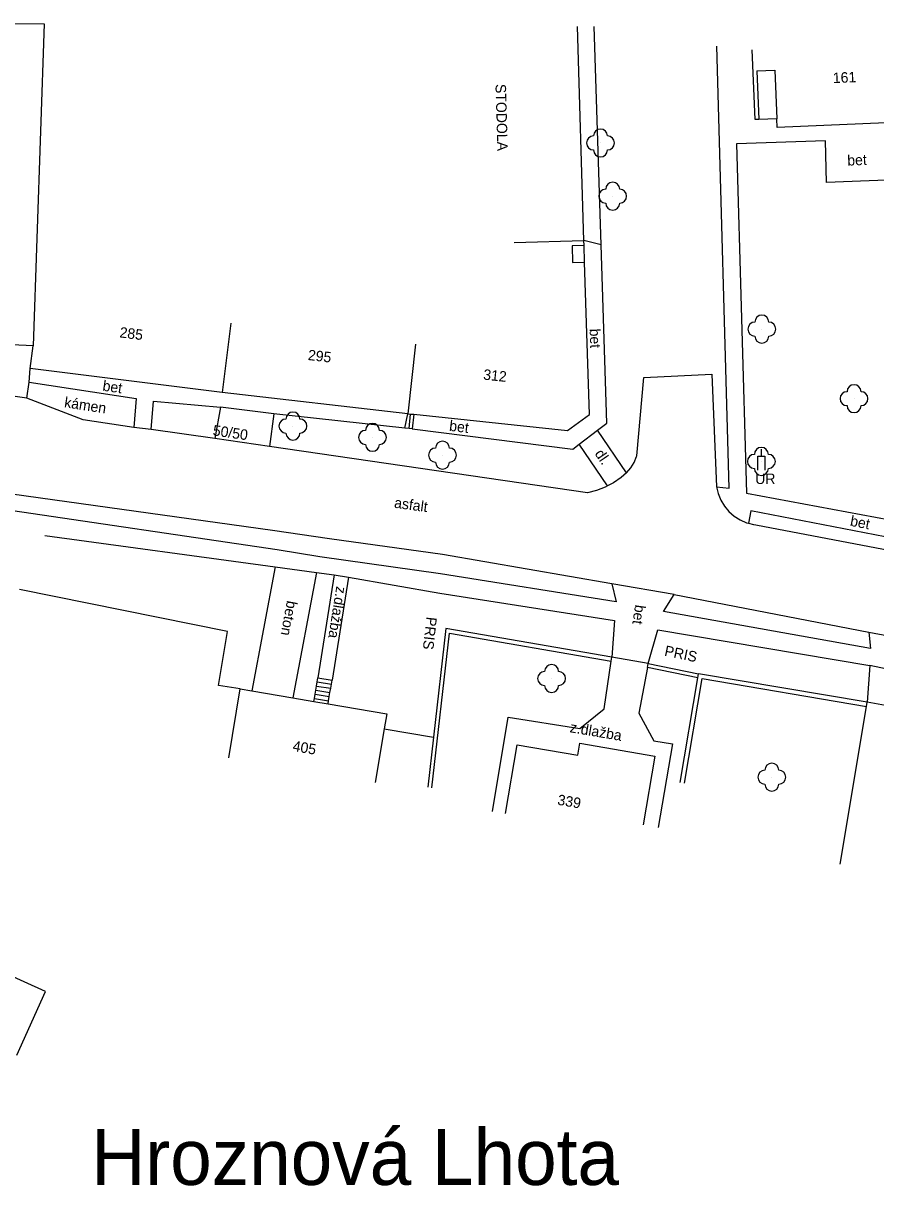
# Model space of a CAD drawing. Extents: x -544674 to -541478, y -1199076 to -1195527.
# Drawn here: x -542446 to -542385, y -1198636.5 to -1198553.3 of the extents above; entities that cross this region are included whole.
import ezdxf

# ---------------------------------------------------------------- set-up
doc = ezdxf.new("R2010")
doc.units = 0
for name, color, linetype in [('BUDOVY_MĚŘ', 7, 'Continuous'), ('BUDOVY_NEMĚŘ', 7, 'Continuous'), ('NÁZVY_SÍDEL_JEDNOTKY', 7, 'Continuous'), ('POMOC_POPIS', 7, 'Continuous'), ('ROZHRANÍ_PLOCH', 7, 'Continuous'), ('ZELEŇ', 7, 'Continuous'), ('ZN_DOPLŇKOVÉ', 7, 'Continuous'), ('Č_POPIS_ORIENT', 7, 'Continuous')]:
    doc.layers.add(name, color=color, linetype=linetype)

msp = doc.modelspace()

# ---------------------------------------------------------------- linework, layer by layer
at = {"layer": 'BUDOVY_MĚŘ'}
for points in [[(-542405.91, -1198568.84), (-542406.36, -1198553.52)], [(-542393.39, -1198560.18), (-542393.65, -1198560.19), (-542393.86, -1198555.2)], [(-542392.1, -1198560.12), (-542393.39, -1198560.18)], [(-542382.62, -1198560.35), (-542392.07, -1198560.75), (-542392.1, -1198560.12)], [(-542410.91, -1198568.99), (-542405.91, -1198568.84)], [(-542405.9, -1198569.2), (-542406.76, -1198569.23), (-542406.72, -1198570.42), (-542405.86, -1198570.39)], [(-542405.9, -1198569.2), (-542405.91, -1198568.84)], [(-542405.86, -1198570.39), (-542405.9, -1198569.2)], [(-542418.09, -1198581.28), (-542407.08, -1198582.45), (-542405.5, -1198581.29), (-542405.86, -1198570.39)], [(-542431.17, -1198574.75), (-542431.79, -1198579.71)], [(-542445.33, -1198576.39), (-542457.12, -1198575.82)], [(-542445.53, -1198578), (-542445.33, -1198576.39)], [(-542417.97, -1198576.27), (-542418.5, -1198581.24)], [(-542431.79, -1198579.71), (-542445.53, -1198578)], [(-542418.5, -1198581.24), (-542431.79, -1198579.71)], [(-542418.5, -1198581.24), (-542418.31, -1198581.26)], [(-542418.31, -1198581.26), (-542418.09, -1198581.28)], [(-542431.33, -1198605.87), (-542430.5, -1198600.94)], [(-542430.5, -1198600.94), (-542429.68, -1198601.08)], [(-542429.68, -1198601.08), (-542426.74, -1198601.58)], [(-542426.74, -1198601.58), (-542425.23, -1198601.83)], [(-542425.23, -1198601.83), (-542424.22, -1198602)], [(-542424.22, -1198602), (-542420.02, -1198602.71), (-542420.2, -1198603.79)], [(-542420.2, -1198603.79), (-542420.85, -1198607.64)], [(-542411.53, -1198609.86), (-542410.69, -1198604.93), (-542406.34, -1198605.67), (-542406.2, -1198604.83), (-542400.84, -1198605.74), (-542401.68, -1198610.67)], [(-542446.48, -1198627.16), (-542444.43, -1198622.6), (-542457.73, -1198616.59), (-542462.9, -1198628.04), (-542468.83, -1198625.36), (-542470.08, -1198628.13), (-542475.77, -1198625.55), (-542478.86, -1198632.49)]]:
    msp.add_lwpolyline(points, dxfattribs=at)
at = {"layer": 'BUDOVY_NEMĚŘ'}
msp.add_lwpolyline([(-542463.23, -1198565.44), (-542463.38, -1198567.01), (-542456.99, -1198567.62), (-542456.68, -1198564.4), (-542454.54, -1198564.6), (-542453.46, -1198553.29), (-542444.54, -1198553.32), (-542445.33, -1198576.39)], dxfattribs=at)
at = {"layer": 'ROZHRANÍ_PLOCH'}
for points in [[(-542404.67, -1198569.15), (-542405.17, -1198553.52)], [(-542396.41, -1198586.46), (-542395.51, -1198586.57), (-542396.39, -1198554.92)], [(-542393.54, -1198556.69), (-542392.24, -1198556.64)], [(-542393.54, -1198556.69), (-542393.39, -1198560.18)], [(-542392.24, -1198556.64), (-542392.1, -1198560.12)], [(-542382.62, -1198560.35), (-542382.44, -1198564.45), (-542388.56, -1198564.68), (-542388.63, -1198561.71), (-542394.99, -1198561.92), (-542394.27, -1198586.92), (-542371.71, -1198591.13), (-542371.39, -1198572.75), (-542373.05, -1198561.12), (-542375.01, -1198561.22), (-542375.06, -1198560.04)], [(-542404.67, -1198569.15), (-542405.91, -1198568.84)], [(-542404.93, -1198582.42), (-542404.27, -1198581.92), (-542404.67, -1198569.15)], [(-542445.77, -1198580.13), (-542468.76, -1198576.82)], [(-542445.6, -1198578.99), (-542445.53, -1198578)], [(-542402.85, -1198585.46), (-542402.55, -1198585.12), (-542402.31, -1198584.73), (-542402.14, -1198584.3), (-542402.13, -1198584.25), (-542401.61, -1198578.64), (-542396.75, -1198578.4), (-542396.41, -1198586.46)], [(-542445.77, -1198580.13), (-542445.6, -1198578.99)], [(-542445.6, -1198578.99), (-542437.95, -1198580.15), (-542438.11, -1198582.22)], [(-542438.11, -1198582.22), (-542441.74, -1198581.67), (-542445.77, -1198580.13)], [(-542436.87, -1198582.37), (-542436.71, -1198580.34), (-542431.92, -1198580.77)], [(-542431.92, -1198580.77), (-542432.31, -1198583.01)], [(-542428.11, -1198581.25), (-542431.92, -1198580.77)], [(-542428.11, -1198581.25), (-542428.42, -1198583.58)], [(-542418.72, -1198582.27), (-542428.11, -1198581.25)], [(-542418.72, -1198582.27), (-542418.5, -1198581.24)], [(-542436.87, -1198582.37), (-542438.11, -1198582.22)], [(-542432.31, -1198583.01), (-542436.87, -1198582.37)], [(-542418.42, -1198582.3), (-542418.72, -1198582.27)], [(-542418.2, -1198582.32), (-542406.71, -1198583.77), (-542406.25, -1198583.42)], [(-542406.25, -1198583.42), (-542404.93, -1198582.42)], [(-542402.85, -1198585.46), (-542404.93, -1198582.42)], [(-542428.42, -1198583.58), (-542432.31, -1198583.01)], [(-542404.21, -1198586.4), (-542404.38, -1198586.49), (-542405.01, -1198586.73), (-542405.66, -1198586.9), (-542428.42, -1198583.58)], [(-542404.21, -1198586.4), (-542406.25, -1198583.42)], [(-542402.85, -1198585.46), (-542403.24, -1198585.8), (-542403.79, -1198586.18), (-542404.21, -1198586.4)], [(-542396.41, -1198586.46), (-542396.3, -1198586.95), (-542396.12, -1198587.42), (-542395.86, -1198587.85), (-542395.54, -1198588.24), (-542395.16, -1198588.57), (-542394.73, -1198588.84), (-542394.27, -1198589.04), (-542394.12, -1198589.07)], [(-542403.91, -1198593.41), (-542416.02, -1198591.31), (-542424.11, -1198590.2), (-542428.2, -1198589.59), (-542446.85, -1198587), (-542447.58, -1198588.07)], [(-542403.91, -1198593.41), (-542403.6, -1198594.71), (-542416.17, -1198592.7), (-542424.81, -1198591.48), (-542427.85, -1198590.99), (-542447.58, -1198588.07)], [(-542372.45, -1198593.23), (-542371.79, -1198592.49), (-542393.96, -1198588.19), (-542394.12, -1198589.07)], [(-542394.12, -1198589.07), (-542393.78, -1198589.16), (-542393.61, -1198589.18), (-542372.45, -1198593.23)], [(-542444.48, -1198589.95), (-542428.01, -1198592.19)], [(-542428.01, -1198592.19), (-542429.68, -1198601.08)], [(-542428.01, -1198592.19), (-542425.05, -1198592.6)], [(-542425.05, -1198592.6), (-542426.74, -1198601.58)], [(-542425.05, -1198592.6), (-542423.77, -1198592.77)], [(-542423.77, -1198592.77), (-542424.94, -1198600.14)], [(-542423.77, -1198592.77), (-542422.76, -1198592.93)], [(-542422.76, -1198592.93), (-542423.93, -1198600.3)], [(-542422.76, -1198592.93), (-542416.21, -1198594.09), (-542403.72, -1198596.03), (-542403.92, -1198598.66)], [(-542399.44, -1198594.18), (-542403.91, -1198593.41)], [(-542385.53, -1198596.88), (-542385.41, -1198598.05), (-542400.22, -1198595.39), (-542399.44, -1198594.18)], [(-542399.44, -1198594.18), (-542385.53, -1198596.88)], [(-542401.3, -1198599.12), (-542400.63, -1198596.71), (-542385.44, -1198599.27)], [(-542385.53, -1198596.88), (-542381.04, -1198597.7)], [(-542412.46, -1198609.7), (-542411.32, -1198602.96), (-542406.2, -1198603.78), (-542404.47, -1198602.35), (-542403.97, -1198598.96)], [(-542401.36, -1198599.41), (-542401.97, -1198602.68), (-542400.9, -1198604.66), (-542399.58, -1198604.86), (-542400.6, -1198610.85)], [(-542385.44, -1198599.27), (-542385.63, -1198601.89)], [(-542381.97, -1198599.99), (-542385.44, -1198599.27)], [(-542424.99, -1198600.44), (-542424.94, -1198600.14)], [(-542424.94, -1198600.14), (-542423.93, -1198600.3)], [(-542425.14, -1198601.32), (-542425.09, -1198601.03)], [(-542425.09, -1198601.03), (-542425.04, -1198600.73)], [(-542425.09, -1198601.03), (-542424.08, -1198601.19)], [(-542425.04, -1198600.73), (-542424.99, -1198600.44)], [(-542425.04, -1198600.73), (-542424.03, -1198600.89)], [(-542424.99, -1198600.44), (-542423.98, -1198600.6)], [(-542424.08, -1198601.19), (-542424.03, -1198600.89)], [(-542424.03, -1198600.89), (-542423.98, -1198600.6)], [(-542423.98, -1198600.6), (-542423.93, -1198600.3)], [(-542425.23, -1198601.83), (-542425.19, -1198601.62)], [(-542425.19, -1198601.62), (-542425.14, -1198601.32)], [(-542425.19, -1198601.62), (-542424.18, -1198601.78)], [(-542425.14, -1198601.32), (-542424.13, -1198601.48)], [(-542424.22, -1198602), (-542424.18, -1198601.78)], [(-542424.18, -1198601.78), (-542424.13, -1198601.48)], [(-542424.13, -1198601.48), (-542424.08, -1198601.19)], [(-542387.57, -1198613.49), (-542385.68, -1198602.19)], [(-542420.2, -1198603.79), (-542416.67, -1198604.38)]]:
    msp.add_lwpolyline(points, dxfattribs=at)
at = {"layer": 'ZELEŇ'}
for centre in [(-542404.72, -1198561.86), (-542403.85, -1198565.67), (-542393.18, -1198575.18), (-542386.58, -1198580.16), (-542426.73, -1198582.12), (-542421.04, -1198582.93), (-542416.03, -1198584.2), (-542393.21, -1198584.65), (-542408.22, -1198600.19), (-542392.46, -1198607.25)]:
    msp.add_circle(centre, 0.0005, dxfattribs=at)
for centre, start, end in [((-542404.72, -1198561.36), 0, 179.99999), ((-542405.22, -1198561.86), 89.99999, 269.99999), ((-542404.22, -1198561.86), 270, 89.99999), ((-542404.72, -1198562.36), 179.99999, 359.99999), ((-542404.35, -1198565.67), 89.99999, 269.99999), ((-542403.85, -1198565.17), 0, 179.99999), ((-542403.35, -1198565.67), 270, 89.99999), ((-542403.85, -1198566.17), 179.99999, 359.99999), ((-542393.18, -1198574.68), 0, 179.99999), ((-542393.68, -1198575.18), 89.99999, 269.99999), ((-542392.68, -1198575.18), 270, 89.99999), ((-542393.18, -1198575.68), 179.99999, 359.99999), ((-542386.58, -1198579.66), 0, 179.99999), ((-542387.08, -1198580.16), 89.99999, 269.99999), ((-542386.08, -1198580.16), 270, 89.99999), ((-542426.73, -1198581.62), 0, 179.99999), ((-542386.58, -1198580.66), 179.99999, 359.99999), ((-542427.23, -1198582.12), 89.99999, 269.99999), ((-542426.23, -1198582.12), 270, 89.99999), ((-542421.04, -1198582.43), 0, 179.99999), ((-542426.73, -1198582.62), 179.99999, 359.99999), ((-542421.54, -1198582.93), 89.99999, 269.99999), ((-542420.54, -1198582.93), 270, 89.99999), ((-542421.04, -1198583.43), 179.99999, 359.99999), ((-542416.03, -1198583.7), 0, 179.99999), ((-542393.21, -1198584.15), 0, 179.99999), ((-542416.53, -1198584.2), 89.99999, 269.99999), ((-542415.53, -1198584.2), 270, 89.99999), ((-542393.71, -1198584.65), 89.99999, 269.99999), ((-542392.71, -1198584.65), 270, 89.99999), ((-542416.03, -1198584.7), 179.99999, 359.99999), ((-542393.21, -1198585.15), 179.99999, 359.99999), ((-542408.22, -1198599.69), 0, 179.99999), ((-542408.72, -1198600.19), 89.99999, 269.99999), ((-542407.72, -1198600.19), 270, 89.99999), ((-542408.22, -1198600.69), 179.99999, 359.99999), ((-542392.96, -1198607.25), 89.99999, 269.99999), ((-542392.46, -1198606.75), 0, 179.99999), ((-542391.96, -1198607.25), 270, 89.99999), ((-542392.46, -1198607.75), 179.99999, 359.99999)]:
    msp.add_arc(centre, 0.5, start, end, dxfattribs=at)
at = {"layer": 'ZN_DOPLŇKOVÉ'}
msp.add_line((-542393.21, -1198584.27), (-542393.21, -1198583.77), dxfattribs=at)
for points in [[(-542418.42, -1198582.3), (-542418.31, -1198581.26)], [(-542418.09, -1198581.28), (-542418.2, -1198582.32)], [(-542418.2, -1198582.32), (-542418.42, -1198582.3)], [(-542393.46, -1198585.27), (-542393.46, -1198584.27), (-542392.96, -1198584.27), (-542392.96, -1198585.27)], [(-542430.5, -1198600.94), (-542432.07, -1198600.69), (-542431.41, -1198596.82), (-542446.29, -1198593.81)], [(-542416.78, -1198608.01), (-542415.52, -1198596.95), (-542403.97, -1198598.96)], [(-542403.92, -1198598.66), (-542415.78, -1198596.6), (-542416.67, -1198604.38)], [(-542403.97, -1198598.96), (-542403.92, -1198598.66)], [(-542401.3, -1198599.12), (-542403.92, -1198598.66)], [(-542401.36, -1198599.41), (-542401.3, -1198599.12)], [(-542397.75, -1198600.15), (-542401.36, -1198599.41)], [(-542401.3, -1198599.12), (-542397.7, -1198599.85)], [(-542399.02, -1198607.63), (-542397.75, -1198600.15)], [(-542398.72, -1198607.68), (-542397.45, -1198600.2), (-542385.68, -1198602.19)], [(-542397.75, -1198600.15), (-542397.7, -1198599.85)], [(-542385.63, -1198601.89), (-542397.7, -1198599.85)], [(-542385.68, -1198602.19), (-542385.63, -1198601.89)], [(-542382.75, -1198602.4), (-542385.63, -1198601.89)], [(-542416.67, -1198604.38), (-542417.08, -1198607.97)]]:
    msp.add_lwpolyline(points, dxfattribs=at)

# ---------------------------------------------------------------- texts
at = {"layer": 'NÁZVY_SÍDEL_JEDNOTKY'}
msp.add_text('Hroznová Lhota', height=4, dxfattribs=at).set_placement((-542441.16, -1198636.44))
at = {"layer": 'POMOC_POPIS'}
for s, rotation, p in [('STODOLA', 271.69, (-542412.24, -1198557.65)), ('bet', 2.15002, (-542387.05, -1198563.48)), ('bet', 271.89002, (-542405.5, -1198575.16)), ('bet', 351.36998, (-542440.39, -1198579.58)), ('kámen', 351.38, (-542443.13, -1198580.77)), ('bet', 352.82999, (-542415.58, -1198582.45)), ('50/50', 351.7, (-542432.5, -1198582.78)), ('dl.', 304.35999, (-542405.17, -1198584.1)), ('asfalt', 352.18999, (-542419.52, -1198587.96)), ('bet', 349.01999, (-542386.9, -1198589.25)), ('z.dlažba', 260.97998, (-542423.62, -1198593.56)), ('beton', 259.34998, (-542427.15, -1198594.58)), ('bet', 261.63997, (-542402.24, -1198594.88)), ('PRIS', 263.52999, (-542417.17, -1198595.75)), ('PRIS', 348.23, (-542400.19, -1198598.55)), ('z.dlažba', 350.36002, (-542406.95, -1198604.03))]:
    msp.add_text(s, height=0.75, rotation=rotation, dxfattribs=at).set_placement(p)
msp.add_text('UR', height=0.75, dxfattribs=at).set_placement((-542393.65, -1198586.27))
at = {"layer": 'Č_POPIS_ORIENT'}
for s, rotation, p in [('161', 2.42, (-542388.08, -1198557.58)), ('285', 352.90997, (-542439.17, -1198575.77)), ('295', 353.42999, (-542425.69, -1198577.39)), ('312', 353.95001, (-542413.14, -1198578.79)), ('405', 350.40999, (-542426.79, -1198605.37)), ('339', 350.36999, (-542407.84, -1198609.22))]:
    msp.add_text(s, height=0.75, rotation=rotation, dxfattribs=at).set_placement(p)

doc.saveas('drawing.dxf')
